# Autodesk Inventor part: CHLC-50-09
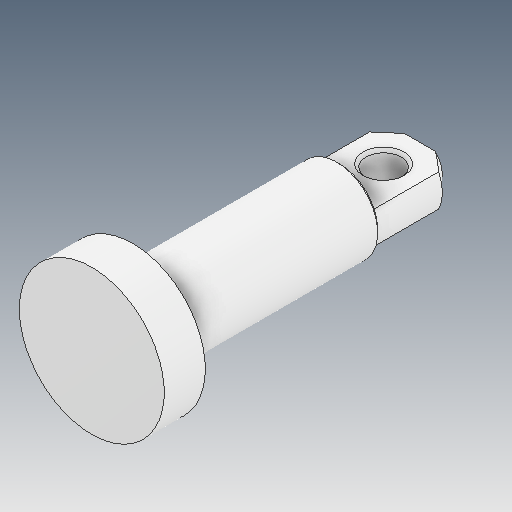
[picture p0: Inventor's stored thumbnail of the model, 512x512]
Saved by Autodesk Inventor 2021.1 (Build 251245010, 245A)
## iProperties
Created: 2021-05
Part Number: CHLC-50-09
Material: Ogólny
Document SubType Name: Modeling
Designer: user
Density: 1 g/cm^3
Appearance: Domyślna
Author: user
Revision Number: ÈÎºÎ
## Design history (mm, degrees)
feature "µ¹½Ç2"
node "Bryła1"
